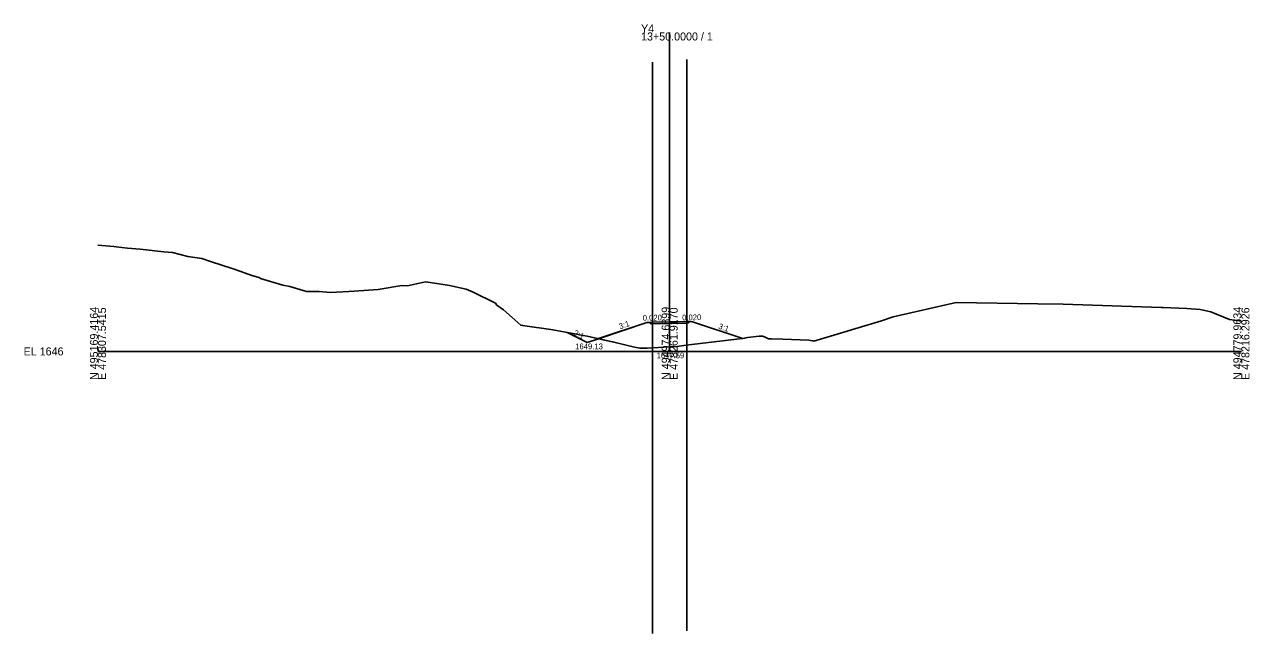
# Model space of a CAD drawing. Extents: x -26 to 403, y -10 to 5108.
# Drawn here: x -25.7 to 402.8, y 3401.3 to 3614.4 of the extents above; entities that cross this region are included whole.
import ezdxf

# ---------------------------------------------------------------- set-up
doc = ezdxf.new("R2010")
doc.units = 0
for name, color, linetype in [('Exist Cross Section Cell', 7, 'Continuous'), ('Exist XS Center Line Elevation Label', 7, 'Continuous'), ('Exist XS Ground Line', 7, 'Continuous'), ('Prop XS DDE', 7, 'Continuous'), ('Prop XS DDE Earthwork Shape', 7, 'Continuous'), ('Prop XS DDE Elevations', 7, 'Continuous'), ('Prop XS DDE Slope Text', 7, 'Continuous'), ('Prop XS Dump Level', 7, 'Continuous'), ('Prop XS Earthwork Shape', 7, 'Continuous'), ('Prop XS EOT Tick Mark', 7, 'Continuous'), ('Prop XS Finish Grade', 7, 'Continuous'), ('Prop XS Finish Grade Earthwork', 7, 'Continuous'), ('Prop XS Finish Grade Pavement', 7, 'Continuous'), ('Prop XS Hydro Fill Slope Data', 7, 'Continuous'), ('Prop XS Pvmt Edge Slope', 7, 'Continuous'), ('Prop XS SE Text', 7, 'Continuous'), ('Prop XS Shoulder Borrow Shape', 7, 'Continuous'), ('Prop XS Side Slope Text', 7, 'Continuous'), ('Prop XS Subgrade Earthwork', 7, 'Continuous'), ('Scratch_Level_1', 7, 'Continuous')]:
    doc.layers.add(name, color=color, linetype=linetype)

msp = doc.modelspace()

# ---------------------------------------------------------------- linework, layer by layer
at = {"layer": 'Exist Cross Section Cell'}
for p, q in [((200, 3500), (200, 3611.64)), ((0, 3500), (200, 3500)), ((200, 3500), (400, 3500))]:
    msp.add_line(p, q, dxfattribs=at)
at = {"layer": 'Exist XS Ground Line'}
msp.add_lwpolyline([(0, 3537.21), (5.52, 3536.68), (6.43, 3536.59), (10.29, 3536.19), (14.75, 3535.77), (15.8, 3535.66), (23.08, 3534.89), (26.07, 3534.61), (31.4, 3533.28), (36.34, 3532.48), (39.72, 3531.37), (46.62, 3529.15), (48.04, 3528.71), (54.14, 3526.5), (56.37, 3525.83), (56.89, 3525.58), (64.69, 3523.17), (67.16, 3522.72), (73.01, 3520.93), (77.43, 3521), (81.34, 3520.65), (87.71, 3520.93), (89.66, 3521.08), (97.98, 3521.62), (106.3, 3523.03), (108.25, 3522.93), (114.63, 3524.32), (118.53, 3523.82), (122.95, 3523.07), (128.8, 3521.83), (131.27, 3520.7), (139.07, 3516.9), (139.59, 3516.23), (141.83, 3514.55), (147.92, 3509.14), (149.34, 3508.93), (158.39, 3507.72), (166.82, 3506.12), (169.57, 3505.56), (171.11, 3505.37), (180.47, 3503.27), (187.74, 3501.51), (189.62, 3501.19), (190.59, 3501.09), (192.1, 3501.15), (200, 3501.59), (202.45, 3501.73), (205.78, 3502.13), (225.34, 3504.51), (226.09, 3504.63), (227.24, 3504.86), (231.33, 3505.38), (232.51, 3505.29), (233.38, 3504.95), (234.55, 3504.35), (235.15, 3504.45), (235.63, 3504.41), (239.61, 3504.29), (248.66, 3503.99), (249.29, 3503.85), (250.05, 3503.75), (250.39, 3503.63), (274.07, 3510.71), (278.21, 3512.16), (300.26, 3517.14), (328.78, 3516.62), (337.66, 3516.58), (371.92, 3515.35), (372.61, 3515.33), (375.35, 3515.24), (380.96, 3515.05), (385.62, 3514.65), (389.28, 3513.87), (395.89, 3511.21), (397.6, 3510.92), (400, 3510.6)], dxfattribs=at)
at = {"layer": 'Prop XS DDE'}
for p, q in [((171.15, 3503.13), (164.16, 3506.62)), ((175.15, 3504.46), (171.15, 3503.13))]:
    msp.add_line(p, q, dxfattribs=at)
at = {"layer": 'Prop XS DDE Earthwork Shape'}
for points in [[(164.16, 3506.62), (166.82, 3506.12), (169.57, 3505.56), (171.11, 3505.37), (175.15, 3504.46), (171.15, 3503.13)], [(171.15, 3503.13), (164.16, 3506.62), (166.82, 3506.12), (169.57, 3505.56), (171.11, 3505.37), (175.15, 3504.46)]]:
    msp.add_lwpolyline(points, close=True, dxfattribs=at)
at = {"layer": 'Prop XS Dump Level'}
for p, q in [((194, 3510.24), (200, 3510.36)), ((200, 3510.36), (206, 3510.48))]:
    msp.add_line(p, q, dxfattribs=at)
at = {"layer": 'Prop XS Earthwork Shape'}
for points in [[(208, 3510.4), (225.56, 3504.55), (225.34, 3504.51), (205.78, 3502.13), (202.45, 3501.73), (200, 3501.59), (192.1, 3501.15), (190.59, 3501.09), (189.62, 3501.19), (187.74, 3501.51), (180.47, 3503.27), (175.15, 3504.46), (192, 3510.08), (192.98, 3510.16), (193.45, 3509.69), (194, 3509.7), (200, 3509.82), (206, 3509.94), (206.53, 3509.95), (207.02, 3510.44)], [(171.15, 3503.13), (164.16, 3506.62), (166.82, 3506.12), (169.57, 3505.56), (171.11, 3505.37), (175.15, 3504.46)]]:
    msp.add_lwpolyline(points, close=True, dxfattribs=at)
at = {"layer": 'Prop XS EOT Tick Mark'}
for p, q in [((194, 3510.24), (194, 3511.24)), ((206, 3510.48), (206, 3511.48))]:
    msp.add_line(p, q, dxfattribs=at)
at = {"layer": 'Prop XS Finish Grade'}
for p, q in [((194, 3510.24), (192.98, 3510.16)), ((206, 3510.48), (207.02, 3510.44))]:
    msp.add_line(p, q, dxfattribs=at)
at = {"layer": 'Prop XS Finish Grade Earthwork'}
for p, q in [((192, 3510.08), (175.15, 3504.46)), ((192.98, 3510.16), (192, 3510.08)), ((207.02, 3510.44), (208, 3510.4)), ((208, 3510.4), (225.56, 3504.55))]:
    msp.add_line(p, q, dxfattribs=at)
at = {"layer": 'Prop XS Finish Grade Pavement'}
for p, q in [((194, 3510.24), (200, 3510.36)), ((200, 3510.36), (206, 3510.48))]:
    msp.add_line(p, q, dxfattribs=at)
at = {"layer": 'Prop XS Hydro Fill Slope Data'}
msp.add_line((192, 3510.09), (175.14, 3504.47), dxfattribs=at)
at = {"layer": 'Prop XS Pvmt Edge Slope'}
for p, q in [((194, 3510.24), (193.45, 3509.69)), ((206, 3510.48), (206.53, 3509.95))]:
    msp.add_line(p, q, dxfattribs=at)
at = {"layer": 'Prop XS Shoulder Borrow Shape'}
for points in [[(194, 3510.24), (192.98, 3510.16), (193.45, 3509.69)], [(206, 3510.48), (207.02, 3510.44), (206.53, 3509.95)]]:
    msp.add_lwpolyline(points, close=True, dxfattribs=at)
at = {"layer": 'Prop XS Subgrade Earthwork'}
for p, q in [((193.45, 3509.69), (192.98, 3510.16)), ((194, 3509.7), (193.45, 3509.69)), ((200, 3509.82), (194, 3509.7)), ((206, 3509.94), (200, 3509.82)), ((206, 3509.94), (206.53, 3509.95)), ((206.53, 3509.95), (207.02, 3510.44))]:
    msp.add_line(p, q, dxfattribs=at)
at = {"layer": 'Scratch_Level_1'}
for p, q in [((194, 3601.26), (194, 3401.26)), ((206, 3602.16), (206, 3402.16))]:
    msp.add_line(p, q, dxfattribs=at)

# ---------------------------------------------------------------- texts
at = {"layer": 'Exist Cross Section Cell'}
for s, p in [('Y4', (190, 3611.64)), ('13+50.0000 / 1', (190, 3608.84)), ('EL 1646', (-26, 3498.6))]:
    msp.add_text(s, height=2.8, dxfattribs=at).set_placement(p)
for s, p in [('N 495169.4164', (0, 3490)), ('E 478307.5415', (2.8, 3490)), ('N 494974.6899', (200, 3490)), ('E 478261.9170', (202.8, 3490)), ('N 494779.9634', (400, 3490)), ('E 478216.2926', (402.8, 3490))]:
    msp.add_text(s, height=2.8, rotation=90, dxfattribs=at).set_placement(p)
at = {"layer": 'Exist XS Center Line Elevation Label'}
msp.add_text('1647.59', height=2, dxfattribs=at).set_placement((195.43, 3497.59))
at = {"layer": 'Prop XS DDE Elevations'}
msp.add_text('1649.13', height=2, dxfattribs=at).set_placement((166.97, 3500.77))
at = {"layer": 'Prop XS DDE Slope Text'}
msp.add_text('2:1', height=2, rotation=333.4355, dxfattribs=at).set_placement((166.17, 3505.84))
at = {"layer": 'Prop XS Dump Level'}
for p in [(192, 3510.04), (208, 3510.36)]:
    msp.add_text('Case1', height=0.04, dxfattribs=at).set_placement(p)
at = {"layer": 'Prop XS SE Text'}
for p in [(190.6, 3510.73), (204.39, 3510.85)]:
    msp.add_text('0.020', height=2, rotation=1.1458, dxfattribs=at).set_placement(p)
at = {"layer": 'Prop XS Side Slope Text'}
for rotation, p in [(18.4349, (182.64, 3507.74)), (341.5651, (216.88, 3508.01))]:
    msp.add_text('3:1', height=2, rotation=rotation, dxfattribs=at).set_placement(p)

doc.saveas('drawing.dxf')
